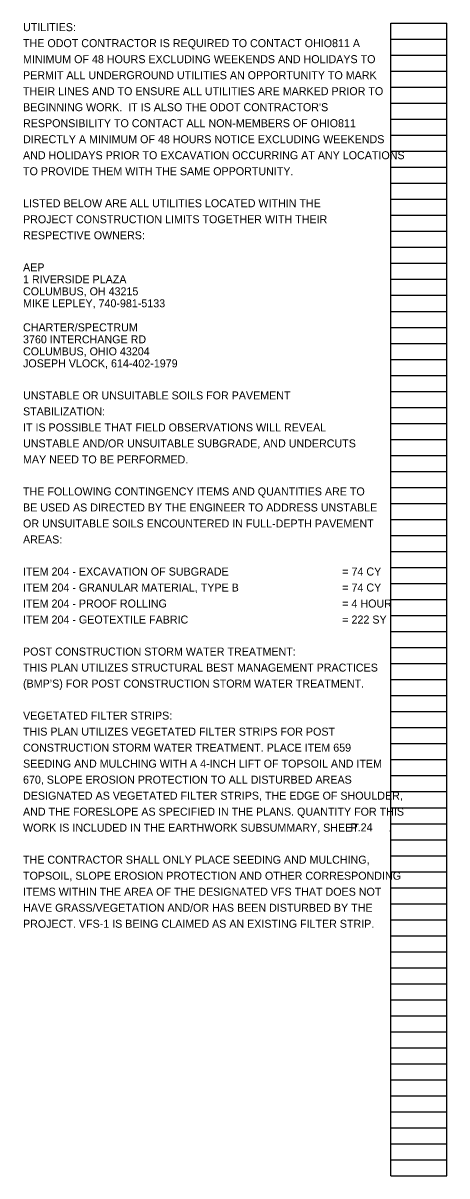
# Model space of a CAD drawing. Extents: x 28758.7 to 28808.5, y 9178.8 to 9230.7.
# Drawn here: x 28786.35 to 28793.77, y 9210.58 to 9230.74 of the extents above; entities that cross this region are included whole.
import ezdxf

# ---------------------------------------------------------------- set-up
doc = ezdxf.new("R2010")
doc.units = 0
for name, color, linetype in [('Default', 7, 'Continuous'), ('SH_Data', 7, 'Continuous'), ('SH_Text', 7, 'Continuous')]:
    doc.layers.add(name, color=color, linetype=linetype)

msp = doc.modelspace()

# ---------------------------------------------------------------- linework, layer by layer
at = {"layer": 'SH_Text'}
for p, q in [((28792.789, 9210.582), (28792.789, 9230.742)), ((28792.789, 9230.742), (28793.769, 9230.742)), ((28793.769, 9210.582), (28793.769, 9230.742)), ((28792.789, 9230.462), (28793.769, 9230.462)), ((28792.789, 9230.182), (28793.769, 9230.182)), ((28792.789, 9229.902), (28793.769, 9229.902)), ((28792.789, 9229.622), (28793.769, 9229.622)), ((28792.789, 9229.342), (28793.769, 9229.342)), ((28792.789, 9229.062), (28793.769, 9229.062)), ((28792.789, 9228.782), (28793.769, 9228.782)), ((28792.789, 9228.502), (28793.769, 9228.502)), ((28792.789, 9228.222), (28793.769, 9228.222)), ((28792.789, 9227.942), (28793.769, 9227.942)), ((28792.789, 9227.662), (28793.769, 9227.662)), ((28792.789, 9227.382), (28793.769, 9227.382)), ((28792.789, 9227.102), (28793.769, 9227.102)), ((28792.789, 9226.822), (28793.769, 9226.822)), ((28792.789, 9226.542), (28793.769, 9226.542)), ((28792.789, 9226.262), (28793.769, 9226.262)), ((28792.789, 9225.982), (28793.769, 9225.982)), ((28792.789, 9225.702), (28793.769, 9225.702)), ((28792.789, 9225.422), (28793.769, 9225.422)), ((28792.789, 9225.142), (28793.769, 9225.142)), ((28792.789, 9224.862), (28793.769, 9224.862)), ((28792.789, 9224.582), (28793.769, 9224.582)), ((28792.789, 9224.302), (28793.769, 9224.302)), ((28792.789, 9224.022), (28793.769, 9224.022)), ((28792.789, 9223.742), (28793.769, 9223.742)), ((28792.789, 9223.462), (28793.769, 9223.462)), ((28792.789, 9223.182), (28793.769, 9223.182)), ((28792.789, 9222.902), (28793.769, 9222.902)), ((28792.789, 9222.622), (28793.769, 9222.622)), ((28792.789, 9222.342), (28793.769, 9222.342)), ((28792.789, 9222.062), (28793.769, 9222.062)), ((28792.789, 9221.782), (28793.769, 9221.782)), ((28792.789, 9221.502), (28793.769, 9221.502)), ((28792.789, 9221.222), (28793.769, 9221.222)), ((28792.789, 9220.942), (28793.769, 9220.942)), ((28792.789, 9220.662), (28793.769, 9220.662)), ((28792.789, 9220.382), (28793.769, 9220.382)), ((28792.789, 9220.102), (28793.769, 9220.102)), ((28792.789, 9219.822), (28793.769, 9219.822)), ((28792.789, 9219.542), (28793.769, 9219.542)), ((28792.789, 9219.262), (28793.769, 9219.262)), ((28792.789, 9218.982), (28793.769, 9218.982)), ((28792.789, 9218.702), (28793.769, 9218.702)), ((28792.789, 9218.422), (28793.769, 9218.422)), ((28792.789, 9218.142), (28793.769, 9218.142)), ((28792.789, 9217.862), (28793.769, 9217.862)), ((28792.789, 9217.582), (28793.769, 9217.582)), ((28792.789, 9217.302), (28793.769, 9217.302)), ((28792.789, 9217.022), (28793.769, 9217.022)), ((28792.789, 9216.742), (28793.769, 9216.742)), ((28792.789, 9216.462), (28793.769, 9216.462)), ((28792.789, 9216.182), (28793.769, 9216.182)), ((28792.789, 9215.902), (28793.769, 9215.902)), ((28792.789, 9215.622), (28793.769, 9215.622)), ((28792.789, 9215.342), (28793.769, 9215.342)), ((28792.789, 9215.062), (28793.769, 9215.062)), ((28792.789, 9214.782), (28793.769, 9214.782)), ((28792.789, 9214.502), (28793.769, 9214.502)), ((28792.789, 9214.222), (28793.769, 9214.222)), ((28792.789, 9213.942), (28793.769, 9213.942)), ((28792.789, 9213.662), (28793.769, 9213.662)), ((28792.789, 9213.382), (28793.769, 9213.382)), ((28792.789, 9213.102), (28793.769, 9213.102)), ((28792.789, 9212.822), (28793.769, 9212.822)), ((28792.789, 9212.542), (28793.769, 9212.542)), ((28792.789, 9212.262), (28793.769, 9212.262)), ((28792.789, 9211.982), (28793.769, 9211.982)), ((28792.789, 9211.702), (28793.769, 9211.702)), ((28792.789, 9211.422), (28793.769, 9211.422)), ((28792.789, 9211.142), (28793.769, 9211.142)), ((28792.789, 9210.862), (28793.769, 9210.862)), ((28792.789, 9210.582), (28793.769, 9210.582))]:
    msp.add_line(p, q, dxfattribs=at)

# ---------------------------------------------------------------- texts
at = {"layer": 'Default'}
for s, p in [('UNSTABLE OR UNSUITABLE SOILS FOR PAVEMENT ', (28786.349, 9224.162)), ('STABILIZATION:', (28786.349, 9223.882))]:
    msp.add_text(s, height=0.14, dxfattribs=at).set_placement(p)
at = {"layer": 'SH_Data'}
for s, p in [('UTILITIES:', (28786.349, 9230.602)), ('THE ODOT CONTRACTOR IS REQUIRED TO CONTACT OHIO811 A ', (28786.349, 9230.322)), ('MINIMUM OF 48 HOURS EXCLUDING WEEKENDS AND HOLIDAYS TO ', (28786.349, 9230.042)), ('PERMIT ALL UNDERGROUND UTILITIES AN OPPORTUNITY TO MARK ', (28786.349, 9229.762)), ('THEIR LINES AND TO ENSURE ALL UTILITIES ARE MARKED PRIOR TO ', (28786.349, 9229.482)), ("BEGINNING WORK.  IT IS ALSO THE ODOT CONTRACTOR'S ", (28786.349, 9229.202)), ('RESPONSIBILITY TO CONTACT ALL NON-MEMBERS OF OHIO811 ', (28786.349, 9228.922)), ('DIRECTLY A MINIMUM OF 48 HOURS NOTICE EXCLUDING WEEKENDS ', (28786.349, 9228.642)), ('AND HOLIDAYS PRIOR TO EXCAVATION OCCURRING AT ANY LOCATIONS ', (28786.349, 9228.362)), ('TO PROVIDE THEM WITH THE SAME OPPORTUNITY.', (28786.349, 9228.082)), ('LISTED BELOW ARE ALL UTILITIES LOCATED WITHIN THE', (28786.349, 9227.522)), ('PROJECT CONSTRUCTION LIMITS TOGETHER WITH THEIR', (28786.349, 9227.242)), ('RESPECTIVE OWNERS:', (28786.349, 9226.962)), ('AEP ', (28786.349, 9226.402)), ('1 RIVERSIDE PLAZA', (28786.349, 9226.192)), ('COLUMBUS, OH 43215', (28786.349, 9225.982)), ('MIKE LEPLEY, 740-981-5133', (28786.349, 9225.772)), ('CHARTER/SPECTRUM', (28786.349, 9225.352)), ('3760 INTERCHANGE RD', (28786.349, 9225.142)), ('COLUMBUS, OHIO 43204', (28786.349, 9224.932)), ('JOSEPH VLOCK, 614-402-1979', (28786.349, 9224.722)), ('IT IS POSSIBLE THAT FIELD OBSERVATIONS WILL REVEAL ', (28786.349, 9223.602)), ('UNSTABLE AND/OR UNSUITABLE SUBGRADE, AND UNDERCUTS ', (28786.349, 9223.322)), ('MAY NEED TO BE PERFORMED.', (28786.349, 9223.042)), ('THE FOLLOWING CONTINGENCY ITEMS AND QUANTITIES ARE TO ', (28786.349, 9222.482)), ('BE USED AS DIRECTED BY THE ENGINEER TO ADDRESS UNSTABLE ', (28786.349, 9222.202)), ('OR UNSUITABLE SOILS ENCOUNTERED IN FULL-DEPTH PAVEMENT ', (28786.349, 9221.922)), ('AREAS:', (28786.349, 9221.642)), ('ITEM 204 - EXCAVATION OF SUBGRADE ', (28786.349, 9221.082)), ('= 74 CY', (28791.937, 9221.082)), ('ITEM 204 - GRANULAR MATERIAL, TYPE B', (28786.349, 9220.802)), ('= 74 CY', (28791.937, 9220.802)), ('ITEM 204 - PROOF ROLLING', (28786.349, 9220.522)), ('= 4 HOUR', (28791.937, 9220.522)), ('ITEM 204 - GEOTEXTILE FABRIC', (28786.349, 9220.242)), ('= 222 SY', (28791.937, 9220.242)), ('POST CONSTRUCTION STORM WATER TREATMENT:', (28786.349, 9219.682)), ('THIS PLAN UTILIZES STRUCTURAL BEST MANAGEMENT PRACTICES ', (28786.349, 9219.402)), ('(BMP’S) FOR POST CONSTRUCTION STORM WATER TREATMENT.', (28786.349, 9219.122)), ('VEGETATED FILTER STRIPS:', (28786.349, 9218.562)), ('THIS PLAN UTILIZES VEGETATED FILTER STRIPS FOR POST ', (28786.349, 9218.282)), ('CONSTRUCTION STORM WATER TREATMENT. PLACE ITEM 659 ', (28786.349, 9218.002)), ('SEEDING AND MULCHING WITH A 4-INCH LIFT OF TOPSOIL AND ITEM ', (28786.349, 9217.722)), ('670, SLOPE EROSION PROTECTION TO ALL DISTURBED AREAS ', (28786.349, 9217.442)), ('DESIGNATED AS VEGETATED FILTER STRIPS, THE EDGE OF SHOULDER, ', (28786.349, 9217.162)), ('AND THE FORESLOPE AS SPECIFIED IN THE PLANS. QUANTITY FOR THIS ', (28786.349, 9216.882)), ('WORK IS INCLUDED IN THE EARTHWORK SUBSUMMARY, SHEET          . ', (28786.349, 9216.602)), ('P.24', (28792.081, 9216.607)), ('THE CONTRACTOR SHALL ONLY PLACE SEEDING AND MULCHING, ', (28786.349, 9216.042)), ('TOPSOIL, SLOPE EROSION PROTECTION AND OTHER CORRESPONDING ', (28786.349, 9215.762)), ('ITEMS WITHIN THE AREA OF THE DESIGNATED VFS THAT DOES NOT ', (28786.349, 9215.482)), ('HAVE GRASS/VEGETATION AND/OR HAS BEEN DISTURBED BY THE ', (28786.349, 9215.202)), ('PROJECT. VFS-1 IS BEING CLAIMED AS AN EXISTING FILTER STRIP.', (28786.349, 9214.922))]:
    msp.add_text(s, height=0.14, dxfattribs=at).set_placement(p)

doc.saveas('drawing.dxf')
